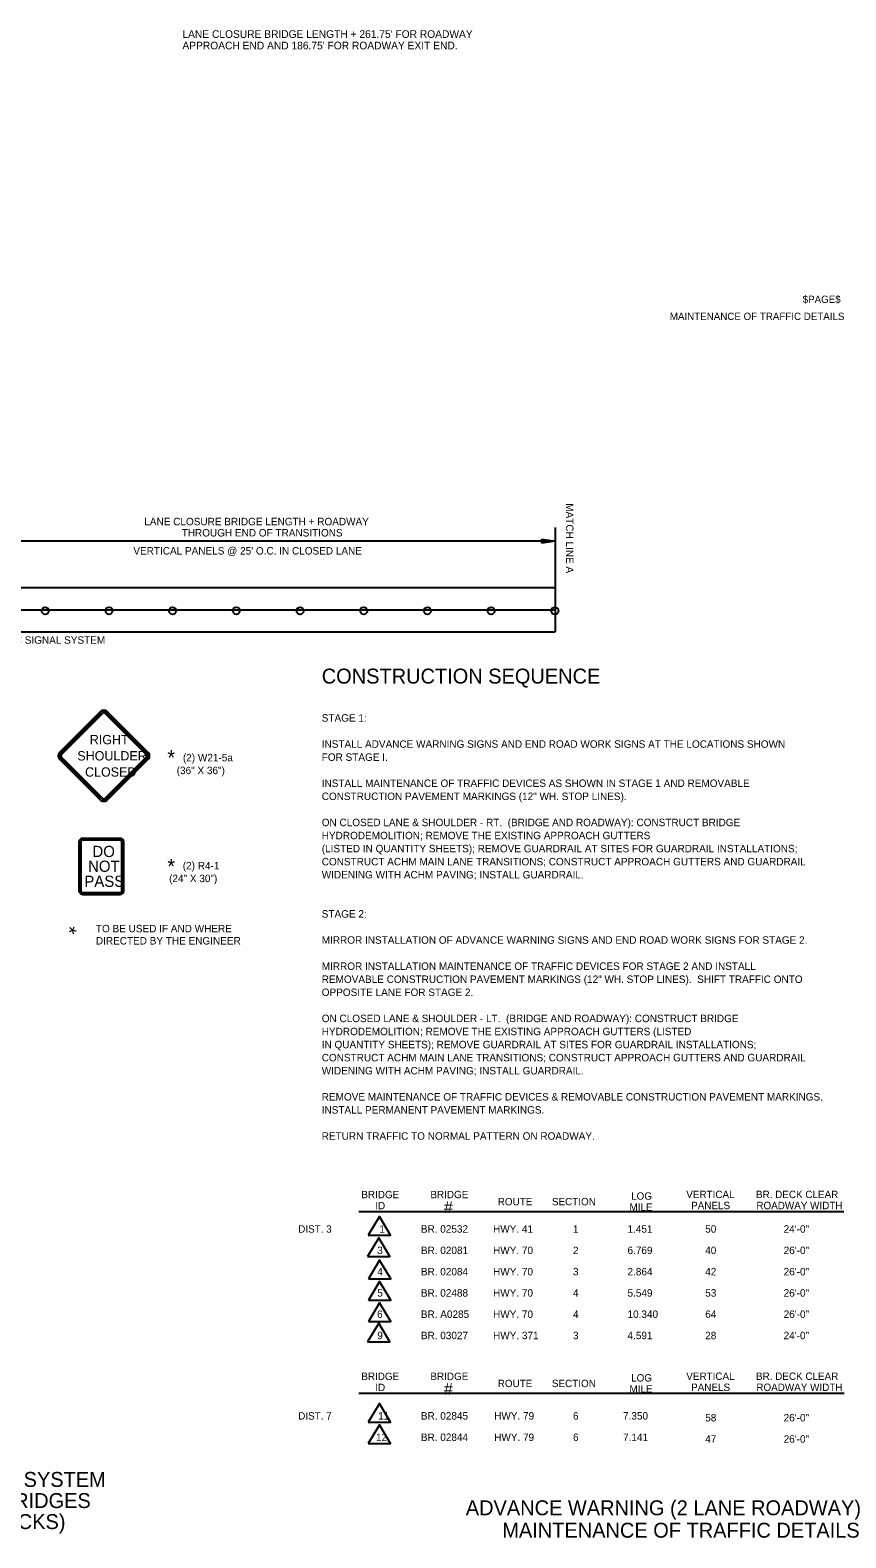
# Model space of a CAD drawing. Extents: x 1926586 to 1930787, y 596452 to 599566.
# Drawn here: x 1928721 to 1929376, y 596676 to 597888 of the extents above; entities that cross this region are included whole.
import ezdxf

# ---------------------------------------------------------------- set-up
doc = ezdxf.new("R2010")
doc.units = 0
for name, color, linetype in [('Default', 7, 'Continuous'), ('P_TC_Signs_Permanent', 7, 'Continuous'), ('P_TC_Signs_Temporary', 7, 'Continuous'), ('R_Border', 7, 'Continuous'), ('R_Border Prem', 7, 'Continuous')]:
    doc.layers.add(name, color=color, linetype=linetype)

msp = doc.modelspace()

# ---------------------------------------------------------------- linework, layer by layer
at = {"layer": 'Default'}
for p, q in [((1929142.1, 597487.8), (1929142.1, 597403.9)), ((1929142.1, 597476.9), (1928697.7, 597476.9)), ((1929131.6, 597475.3), (1929131.6, 597478.5)), ((1929131.6, 597478.5), (1929142.1, 597476.9)), ((1929142.1, 597476.9), (1929131.6, 597475.3)), ((1927870.1, 597439.5), (1929142.1, 597439.5)), ((1927870.1, 597421.7), (1929142.1, 597421.7)), ((1927870.1, 597403.9), (1929142.1, 597403.9)), ((1928992, 596919.1), (1929001, 596919.1)), ((1928991.5, 596901.9), (1929000.5, 596901.9)), ((1928992.2, 596884.1), (1929001.2, 596884.1)), ((1928992.2, 596867), (1929001.2, 596867)), ((1928992.2, 596849.8), (1929001.2, 596849.8)), ((1928991.5, 596833.5), (1929000.5, 596833.5)), ((1928992, 596768.9), (1929001, 596768.9)), ((1928992, 596751.7), (1929001, 596751.7))]:
    msp.add_line(p, q, dxfattribs=at)
for points in [[(1929001, 596919.1), (1929010, 596919.1), (1929001, 596934.1), (1928992, 596919.1)], [(1929000.5, 596901.9), (1929009.5, 596901.9), (1929000.5, 596916.9), (1928991.5, 596901.9)], [(1929001.2, 596884.1), (1929010.2, 596884.1), (1929001.2, 596899.1), (1928992.2, 596884.1)], [(1929001.2, 596867), (1929010.2, 596867), (1929001.2, 596882), (1928992.2, 596867)], [(1929001.2, 596849.8), (1929010.2, 596849.8), (1929001.2, 596864.8), (1928992.2, 596849.8)], [(1929000.5, 596833.5), (1929009.5, 596833.5), (1929000.5, 596848.5), (1928991.5, 596833.5)], [(1929001, 596768.9), (1929010, 596768.9), (1929001, 596783.9), (1928992, 596768.9)], [(1929001, 596751.7), (1929010, 596751.7), (1929001, 596766.7), (1928992, 596751.7)]]:
    msp.add_lwpolyline(points, dxfattribs=at)
for centre in [(1928732.6, 597420.9), (1928783.8, 597420.9), (1928834.9, 597420.9), (1928886.1, 597420.9), (1928937.3, 597420.9), (1928988.4, 597420.9), (1929039.6, 597420.9), (1929090.7, 597420.9), (1929141.9, 597420.9)]:
    msp.add_circle(centre, 2.88, dxfattribs=at)
at = {"layer": 'P_TC_Signs_Permanent'}
for p, q in [((1928759.7, 597235), (1928759.7, 597196)), ((1928760.3, 597235), (1928760.3, 597196)), ((1928761.2, 597235), (1928761.2, 597196)), ((1928792.7, 597238), (1928762.7, 597238)), ((1928792.7, 597237.4), (1928762.7, 597237.4)), ((1928792.7, 597236.5), (1928762.7, 597236.5)), ((1928794.2, 597196), (1928794.2, 597235)), ((1928795.1, 597196), (1928795.1, 597235)), ((1928795.7, 597196), (1928795.7, 597235)), ((1928762.7, 597194.5), (1928792.7, 597194.5)), ((1928762.7, 597193.6), (1928792.7, 597193.6)), ((1928762.7, 597193), (1928792.7, 597193))]:
    msp.add_line(p, q, dxfattribs=at)
for centre, radius, start, end in [((1928762.7, 597235), 3, 90, 180), ((1928762.7, 597235), 2.4, 90, 180), ((1928762.7, 597235), 1.5, 90, 180), ((1928792.7, 597235), 3, 360, 90), ((1928792.7, 597235), 2.4, 360, 90), ((1928792.7, 597235), 1.5, 360, 90), ((1928762.7, 597196), 3, 180, 270), ((1928762.7, 597196), 2.4, 180, 270), ((1928762.7, 597196), 1.5, 180, 270), ((1928792.7, 597196), 3, 270, 360), ((1928792.7, 597196), 2.4, 270, 360), ((1928792.7, 597196), 1.5, 270, 360)]:
    msp.add_arc(centre, radius, start, end, dxfattribs=at)
at = {"layer": 'P_TC_Signs_Temporary'}
for p, q in [((1928743.9, 597306.7), (1928777.3, 597340.1)), ((1928744.5, 597306), (1928777.9, 597339.4)), ((1928745.5, 597305.1), (1928778.9, 597338.5)), ((1928780.5, 597338.5), (1928813.9, 597305.1)), ((1928781.4, 597339.4), (1928814.8, 597306)), ((1928782, 597340.1), (1928815.5, 597306.7)), ((1928777.3, 597268.5), (1928743.9, 597301.9)), ((1928777.9, 597269.2), (1928744.5, 597302.6)), ((1928778.9, 597270.1), (1928745.5, 597303.5)), ((1928813.9, 597303.5), (1928780.5, 597270.1)), ((1928814.8, 597302.6), (1928781.4, 597269.2)), ((1928815.5, 597301.9), (1928782, 597268.5))]:
    msp.add_line(p, q, dxfattribs=at)
for centre, radius, start, end in [((1928779.7, 597337.7), 3.38, 45, 135), ((1928779.7, 597337.7), 2.44, 45, 135), ((1928779.7, 597337.7), 1.13, 45, 135), ((1928746.3, 597304.3), 3.37, 135, 225), ((1928746.3, 597304.3), 2.44, 135, 225), ((1928746.3, 597304.3), 1.12, 135, 225), ((1928813.1, 597304.3), 1.12, 315, 45), ((1928813.1, 597304.3), 2.44, 315, 45), ((1928813.1, 597304.3), 3.37, 315, 45), ((1928779.7, 597270.9), 3.38, 225, 315), ((1928779.7, 597270.9), 2.44, 225, 315), ((1928779.7, 597270.9), 1.13, 225, 315)]:
    msp.add_arc(centre, radius, start, end, dxfattribs=at)
at = {"layer": 'R_Border'}
for p, q in [((1928984.6, 596938.1), (1929374.1, 596938.1)), ((1928984.6, 596792), (1929374.4, 596792))]:
    msp.add_line(p, q, dxfattribs=at)

# ---------------------------------------------------------------- texts
at = {"layer": 'Default'}
for s, height, rotation, p in [("LANE CLOSURE BRIDGE LENGTH + 261.75' FOR ROADWAY ", 6.14, 360, (1928842.8, 597881.3)), ("APPROACH END AND 186.75' FOR ROADWAY EXIT END.", 6.14, 360, (1928842.8, 597872.1)), ('LANE CLOSURE BRIDGE LENGTH + ROADWAY ', 6, 360, (1928812.2, 597489.6)), ('MATCH LINE A', 6, 270, (1929150.9, 597507.3)), ('THROUGH END OF TRANSITIONS', 6, 360, (1928842.2, 597480.6)), ("VERTICAL PANELS @ 25' O.C. IN CLOSED LANE", 6, 360, (1928803.4, 597466.1)), ('PORTABLE TRAFFIC SIGNAL SYSTEM', 6, 360, (1928635, 597394.4)), ('LANE CLOSURE WITH PORTABLE TRAFFIC SIGNAL SYSTEM ', 12, 360, (1928315.8, 596716.8)), ('& TRAFFIC DRUMS FOR HYDRODEMOLITION BRIDGES  ', 12, 360, (1928345.7, 596699.8)), ('(VAR. CLEAR ROADWAY ON THE BRIDGE DECKS)', 12, 360, (1928364.6, 596682.9))]:
    msp.add_text(s, height=height, rotation=rotation, dxfattribs=at).set_placement(p)
at = {"layer": 'P_TC_Signs_Permanent'}
for s, rotation, p in [('DO', 360, (1928770.5, 597223)), ('NOT', 359.9596, (1928767, 597211.1)), ('PASS', 360, (1928764, 597199))]:
    msp.add_text(s, height=9, rotation=rotation, dxfattribs=at).set_placement(p)
at = {"layer": 'P_TC_Signs_Temporary'}
for s, p in [('RIGHT', (1928768.4, 597313.6)), ('SHOULDER', (1928758.4, 597300.6)), ('CLOSED', (1928764.6, 597287.6))]:
    msp.add_text(s, height=7.5, rotation=360, dxfattribs=at).set_placement(p)
at = {"layer": 'R_Border'}
for s, height, rotation, p in [('CONSTRUCTION SEQUENCE', 12, 360, (1928954.7, 597362.4)), ('STAGE 1:', 6, 360, (1928954.7, 597331.8)), ('INSTALL ADVANCE WARNING SIGNS AND END ROAD WORK SIGNS AT THE LOCATIONS SHOWN ', 6, 360, (1928954.7, 597310.8)), ('(2) W21-5a', 6, 360, (1928843.2, 597299.9)), ('FOR STAGE I.  ', 6, 360, (1928954.7, 597300.3)), ('(36" X 36")', 6, 360, (1928838.2, 597289.6)), ('INSTALL MAINTENANCE OF TRAFFIC DEVICES AS SHOWN IN STAGE 1 AND REMOVABLE ', 6, 360, (1928954.7, 597279.3)), ('CONSTRUCTION PAVEMENT MARKINGS (12" WH. STOP LINES). ', 6, 360, (1928954.7, 597268.8)), ('ON CLOSED LANE & SHOULDER - RT.  (BRIDGE AND ROADWAY): CONSTRUCT BRIDGE ', 6, 360, (1928954.7, 597247.8)), ('HYDRODEMOLITION; REMOVE THE EXISTING APPROACH GUTTERS ', 6, 360, (1928954.7, 597237.3)), ('(LISTED IN QUANTITY SHEETS); REMOVE GUARDRAIL AT SITES FOR GUARDRAIL INSTALLATIONS; ', 6, 360, (1928954.7, 597226.8)), ('(2) R4-1', 6, 360, (1928843.1, 597213.1)), ('CONSTRUCT ACHM MAIN LANE TRANSITIONS; CONSTRUCT APPROACH GUTTERS AND GUARDRAIL', 6, 360, (1928954.7, 597216.3)), ('(24" X 30")', 6, 360, (1928832.1, 597202.8)), ('WIDENING WITH ACHM PAVING; INSTALL GUARDRAIL.', 6, 360, (1928954.7, 597205.8)), ('STAGE 2:', 6, 360, (1928954.7, 597174.3)), ('TO BE USED IF AND WHERE', 6, 360, (1928773.3, 597162.5)), ('*', 12, 45, (1928758.6, 597155.7)), ('DIRECTED BY THE ENGINEER', 6, 360, (1928773.3, 597152.7)), ('MIRROR INSTALLATION OF ADVANCE WARNING SIGNS AND END ROAD WORK SIGNS FOR STAGE 2.  ', 6, 360, (1928954.7, 597153.3)), ('MIRROR INSTALLATION MAINTENANCE OF TRAFFIC DEVICES FOR STAGE 2 AND INSTALL ', 6, 360, (1928954.7, 597132.3)), ('REMOVABLE CONSTRUCTION PAVEMENT MARKINGS (12" WH. STOP LINES).  SHIFT TRAFFIC ONTO ', 6, 360, (1928954.7, 597121.8)), ('OPPOSITE LANE FOR STAGE 2.', 6, 360, (1928954.7, 597111.3)), ('ON CLOSED LANE & SHOULDER - LT.  (BRIDGE AND ROADWAY): CONSTRUCT BRIDGE ', 6, 360, (1928954.7, 597090.3)), ('HYDRODEMOLITION; REMOVE THE EXISTING APPROACH GUTTERS (LISTED ', 6, 360, (1928954.7, 597079.8)), ('IN QUANTITY SHEETS); REMOVE GUARDRAIL AT SITES FOR GUARDRAIL INSTALLATIONS; ', 6, 360, (1928954.7, 597069.3)), ('CONSTRUCT ACHM MAIN LANE TRANSITIONS; CONSTRUCT APPROACH GUTTERS AND GUARDRAIL', 6, 360, (1928954.7, 597058.8)), ('WIDENING WITH ACHM PAVING; INSTALL GUARDRAIL.', 6, 360, (1928954.7, 597048.3)), ('REMOVE MAINTENANCE OF TRAFFIC DEVICES & REMOVABLE CONSTRUCTION PAVEMENT MARKINGS.  ', 6, 360, (1928954.7, 597027.3)), ('INSTALL PERMANENT PAVEMENT MARKINGS.', 6, 360, (1928954.7, 597016.8)), ('RETURN TRAFFIC TO NORMAL PATTERN ON ROADWAY. ', 6, 360, (1928954.7, 596995.8)), ('BRIDGE ', 5.93, 360, (1928986.5, 596948.8)), ('BRIDGE ', 5.93, 360, (1929042, 596948.8)), ('LOG', 5.93, 360, (1929203.2, 596947.6)), ('VERTICAL', 5.93, 360, (1929247.5, 596948.9)), ('BR. DECK CLEAR', 5.929, 360, (1929303.5, 596948.9)), ('ID', 5.93, 360, (1928997.7, 596939.9)), ('#', 9.5, 360, (1929052.9, 596936.9)), ('ROUTE', 5.93, 360, (1929096.1, 596943.1)), ('SECTION', 5.93, 360, (1929139.6, 596943.1)), ('MILE', 5.93, 360, (1929201.9, 596938.7)), ('PANELS', 5.93, 360, (1929251.4, 596940)), ('ROADWAY WIDTH', 5.929, 360, (1929303.8, 596940)), ('DIST. 3', 5.93, 360, (1928935.8, 596921.1)), ('1', 6, 360, (1929001, 596921.1)), ('BR. 02532', 6, 360, (1929034.3, 596921.1)), ('HWY. 41', 6, 360, (1929092.3, 596921.1)), ('1', 6, 360, (1929156.5, 596921.1)), ('1.451', 6, 360, (1929200.3, 596921.1)), ('50', 6, 360, (1929262.7, 596921.1)), ('24\'-0"', 6, 360, (1929325.7, 596921.1)), ('3', 6, 360, (1928999.3, 596903.9)), ('BR. 02081', 6, 360, (1929034.3, 596903.9)), ('HWY. 70', 6, 360, (1929092.3, 596903.9)), ('2', 6, 360, (1929156.5, 596903.9)), ('6.769', 6, 360, (1929200.3, 596903.9)), ('40', 6, 360, (1929262.7, 596903.9)), ('26\'-0"', 6, 360, (1929325.7, 596903.9)), ('4', 6, 360, (1928999.3, 596886.8)), ('BR. 02084', 6, 360, (1929034.3, 596886.8)), ('HWY. 70', 6, 360, (1929092.3, 596886.8)), ('3', 6, 360, (1929156.5, 596886.8)), ('2.864', 6, 360, (1929200.3, 596886.8)), ('42', 6, 360, (1929262.7, 596886.8)), ('26\'-0"', 6, 360, (1929325.7, 596886.8)), ('5', 6, 360, (1928999.3, 596869.7)), ('BR. 02488', 6, 360, (1929034.3, 596869.7)), ('HWY. 70', 6, 360, (1929092.3, 596869.7)), ('4', 6, 360, (1929156.5, 596869.7)), ('5.549', 6, 360, (1929200.3, 596869.7)), ('53', 6, 360, (1929262.7, 596869.7)), ('26\'-0"', 6, 360, (1929325.7, 596869.7)), ('6', 6, 360, (1928999.1, 596852.6)), ('BR. A0285', 6, 360, (1929034.3, 596852.6)), ('HWY. 70', 6, 360, (1929092.3, 596852.6)), ('4', 6, 360, (1929156.5, 596852.6)), ('10.340', 6, 360, (1929200.3, 596852.6)), ('64', 6, 360, (1929262.7, 596852.6)), ('26\'-0"', 6, 360, (1929325.7, 596852.6)), ('9', 6, 360, (1928999.3, 596835.5)), ('BR. 03027', 6, 360, (1929034.3, 596835.5)), ('HWY. 371', 6, 360, (1929092.3, 596835.5)), ('3', 6, 360, (1929156.5, 596835.5)), ('4.591', 6, 360, (1929200.3, 596835.5)), ('28', 6, 360, (1929262.7, 596835.5)), ('24\'-0"', 6, 360, (1929325.7, 596835.5)), ('BRIDGE ', 5.93, 360, (1928986.5, 596802.7)), ('BRIDGE ', 5.93, 360, (1929042, 596802.7)), ('LOG', 5.93, 360, (1929203.2, 596801.5)), ('VERTICAL', 5.93, 360, (1929247.5, 596802.8)), ('BR. DECK CLEAR', 5.929, 360, (1929303.5, 596802.8)), ('ID', 5.93, 360, (1928997.7, 596793.8)), ('#', 9.5, 360, (1929052.9, 596790.8)), ('ROUTE', 5.93, 360, (1929096.1, 596797)), ('SECTION', 5.93, 360, (1929139.6, 596797)), ('MILE', 5.93, 360, (1929201.9, 596792.6)), ('PANELS', 5.93, 360, (1929251.4, 596793.9)), ('ROADWAY WIDTH', 5.929, 360, (1929303.8, 596793.9)), ('DIST. 7', 5.93, 360, (1928935.8, 596770.9)), ('11', 6, 360, (1929000, 596770.9)), ('BR. 02845', 6, 360, (1929034.3, 596770.9)), ('HWY. 79', 6, 360, (1929093.2, 596770.9)), ('6', 6, 360, (1929156.5, 596770.9)), ('7.350', 6, 360, (1929196.7, 596770.9)), ('58', 6, 360, (1929262.7, 596769.4)), ('26\'-0"', 6, 360, (1929325.7, 596769.4)), ('12', 6, 360, (1928998.3, 596753.7)), ('BR. 02844', 6, 360, (1929034.3, 596753.7)), ('HWY. 79', 6, 360, (1929093.2, 596753.7)), ('6', 6, 360, (1929156.5, 596753.7)), ('7.141', 6, 360, (1929196.7, 596753.7)), ('47', 6, 360, (1929262.7, 596752.3)), ('26\'-0"', 6, 360, (1929325.7, 596752.3)), ('ADVANCE WARNING (2 LANE ROADWAY)', 12, 360, (1929070.4, 596694)), ('MAINTENANCE OF TRAFFIC DETAILS', 12, 360, (1929099.7, 596676))]:
    msp.add_text(s, height=height, rotation=rotation, dxfattribs=at).set_placement(p)
at = {"layer": 'R_Border Prem'}
for s, height, p in [('$PAGE$', 5.86, (1929341, 597668.3)), ('MAINTENANCE OF TRAFFIC DETAILS', 5.862, (1929234.3, 597654.6)), ('*', 12, (1928830.7, 597296.9)), ('*', 12, (1928830.7, 597209.5))]:
    msp.add_text(s, height=height, rotation=360, dxfattribs=at).set_placement(p)

doc.saveas('drawing.dxf')
